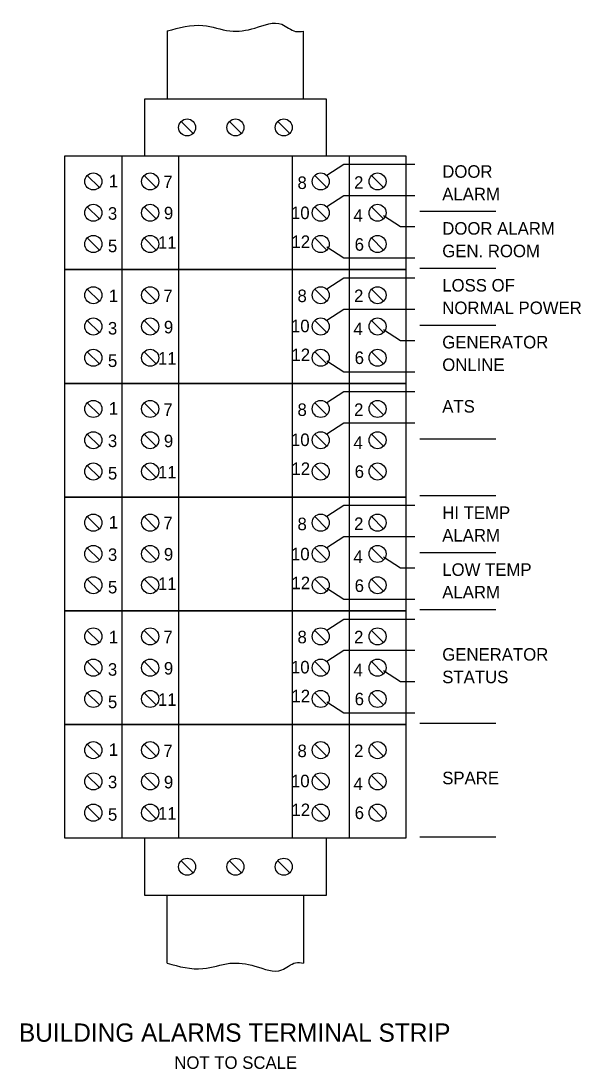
# Model space of a CAD drawing. Extents: x -0.178 to 0.269, y -0.328 to 0.508.
import ezdxf

# ---------------------------------------------------------------- set-up
doc = ezdxf.new("R2010")
doc.units = 0
doc.layers.add('GE_Pr_Notation', color=7, linetype='Continuous')
doc.layers.add('HS_Electrical_Devices', color=7, linetype='Continuous')

msp = doc.modelspace()

# ---------------------------------------------------------------- linework, layer by layer
at = {"layer": 'GE_Pr_Notation'}
for p, q in [((0.14026, 0.35631), (0.20079, 0.35631)), ((0.14026, 0.31091), (0.20079, 0.31091)), ((0.14026, 0.26552), (0.20079, 0.26552)), ((0.14026, 0.17473), (0.20079, 0.17473)), ((0.14026, 0.12938), (0.20079, 0.12938)), ((0.14026, 0.08394), (0.20079, 0.08394)), ((0.14026, 0.03854), (0.20079, 0.03854)), ((0.14026, -0.05225), (0.20079, -0.05225)), ((0.14026, -0.14307), (0.20079, -0.14307))]:
    msp.add_line(p, q, dxfattribs=at)
for points in [[(0.13613, 0.39372), (0.07935, 0.39372), (0.06581, 0.38494)], [(0.13613, 0.36876), (0.07935, 0.36876), (0.06581, 0.35998)], [(0.13613, 0.34379), (0.12475, 0.34379), (0.11121, 0.35257)], [(0.13613, 0.31882), (0.07935, 0.31882), (0.06581, 0.3276)], [(0.13613, 0.30293), (0.07935, 0.30293), (0.06581, 0.29416)], [(0.13613, 0.27797), (0.07935, 0.27797), (0.06581, 0.26919)], [(0.13613, 0.253), (0.12475, 0.253), (0.11121, 0.26178)], [(0.13613, 0.22803), (0.07935, 0.22803), (0.06581, 0.23681)], [(0.13613, 0.21215), (0.07935, 0.21215), (0.06581, 0.20337)], [(0.13613, 0.18718), (0.07935, 0.18718), (0.06581, 0.1784)], [(0.13613, 0.12136), (0.07935, 0.12136), (0.06581, 0.11258)], [(0.13613, 0.09639), (0.07935, 0.09639), (0.06581, 0.08761)], [(0.13613, 0.07142), (0.12475, 0.07142), (0.11121, 0.0802)], [(0.13613, 0.04645), (0.07935, 0.04645), (0.06581, 0.05523)], [(0.13613, 0.03057), (0.07935, 0.03057), (0.06581, 0.02179)], [(0.13613, 0.0056), (0.07935, 0.0056), (0.06581, -0.00318)], [(0.13613, -0.01937), (0.12475, -0.01937), (0.11121, -0.01059)], [(0.13613, -0.04434), (0.07935, -0.04434), (0.06581, -0.03556)]]:
    msp.add_lwpolyline(points, dxfattribs=at)
at = {"layer": 'HS_Electrical_Devices'}
for p, q in [((-0.06157, 0.50031), (-0.06157, 0.44595)), ((0.04738, 0.44595), (0.04738, 0.50021)), ((-0.0505, 0.42807), (-0.04087, 0.41844)), ((-0.01189, 0.42806), (-0.00226, 0.41843)), ((0.02668, 0.42807), (0.03631, 0.41844)), ((-0.09788, 0.40056), (-0.09788, 0.30977)), ((-0.05249, 0.40056), (-0.05249, 0.30977)), ((0.0383, 0.40056), (0.0383, 0.30977)), ((0.08369, 0.40056), (0.08369, 0.30977)), ((-0.1254, 0.38494), (-0.11577, 0.37532)), ((-0.08, 0.38494), (-0.07037, 0.37532)), ((0.05618, 0.38494), (0.06581, 0.37532)), ((0.10158, 0.38494), (0.11121, 0.37532)), ((-0.1254, 0.35998), (-0.11577, 0.35035)), ((-0.08, 0.35998), (-0.07037, 0.35035)), ((0.05618, 0.35998), (0.06581, 0.35035)), ((0.10158, 0.35998), (0.11121, 0.35035)), ((-0.1254, 0.33501), (-0.11577, 0.32538)), ((-0.08, 0.33501), (-0.07037, 0.32538)), ((0.05618, 0.33501), (0.06581, 0.32538)), ((0.10158, 0.33501), (0.11121, 0.32538)), ((-0.09788, 0.30977), (-0.09788, 0.21898)), ((-0.05249, 0.30977), (-0.05249, 0.21898)), ((0.0383, 0.30977), (0.0383, 0.21898)), ((0.08369, 0.30977), (0.08369, 0.21898)), ((-0.1254, 0.29416), (-0.11577, 0.28453)), ((-0.08, 0.29416), (-0.07037, 0.28453)), ((0.05618, 0.29416), (0.06581, 0.28453)), ((0.10158, 0.29416), (0.11121, 0.28453)), ((-0.1254, 0.26919), (-0.11577, 0.25956)), ((-0.08, 0.26919), (-0.07037, 0.25956)), ((0.05618, 0.26919), (0.06581, 0.25956)), ((0.10158, 0.26919), (0.11121, 0.25956)), ((-0.1254, 0.24422), (-0.11577, 0.23459)), ((-0.08, 0.24422), (-0.07037, 0.23459)), ((0.05618, 0.24422), (0.06581, 0.23459)), ((0.10158, 0.24422), (0.11121, 0.23459)), ((-0.09788, 0.21898), (-0.09788, 0.12819)), ((-0.05249, 0.21898), (-0.05249, 0.12819)), ((0.0383, 0.21898), (0.0383, 0.12819)), ((0.08369, 0.21898), (0.08369, 0.12819)), ((-0.1254, 0.20337), (-0.11577, 0.19374)), ((-0.08, 0.20337), (-0.07037, 0.19374)), ((0.05618, 0.20337), (0.06581, 0.19374)), ((0.10158, 0.20337), (0.11121, 0.19374)), ((-0.1254, 0.1784), (-0.11577, 0.16877)), ((-0.08, 0.1784), (-0.07037, 0.16877)), ((0.05618, 0.1784), (0.06581, 0.16877)), ((0.10158, 0.1784), (0.11121, 0.16877)), ((-0.1254, 0.15343), (-0.11577, 0.1438)), ((-0.08, 0.15343), (-0.07037, 0.1438)), ((0.05618, 0.15343), (0.06581, 0.1438)), ((0.10158, 0.15343), (0.11121, 0.1438)), ((-0.09788, 0.12819), (-0.09788, 0.0374)), ((-0.05249, 0.12819), (-0.05249, 0.0374)), ((0.0383, 0.12819), (0.0383, 0.0374)), ((0.08369, 0.12819), (0.08369, 0.0374)), ((-0.1254, 0.11258), (-0.11577, 0.10295)), ((-0.08, 0.11258), (-0.07037, 0.10295)), ((0.05618, 0.11258), (0.06581, 0.10295)), ((0.10158, 0.11258), (0.11121, 0.10295)), ((-0.1254, 0.08761), (-0.11577, 0.07798)), ((-0.08, 0.08761), (-0.07037, 0.07798)), ((0.05618, 0.08761), (0.06581, 0.07798)), ((0.10158, 0.08761), (0.11121, 0.07798)), ((-0.1254, 0.06264), (-0.11577, 0.05301)), ((-0.08, 0.06264), (-0.07037, 0.05301)), ((0.05618, 0.06264), (0.06581, 0.05301)), ((0.10158, 0.06264), (0.11121, 0.05301)), ((-0.09788, 0.0374), (-0.09788, -0.05339)), ((-0.05249, 0.0374), (-0.05249, -0.05339)), ((0.0383, 0.0374), (0.0383, -0.05339)), ((0.08369, 0.0374), (0.08369, -0.05339)), ((-0.1254, 0.02179), (-0.11577, 0.01216)), ((-0.08, 0.02179), (-0.07037, 0.01216)), ((0.05618, 0.02179), (0.06581, 0.01216)), ((0.10158, 0.02179), (0.11121, 0.01216)), ((-0.1254, -0.00318), (-0.11577, -0.01281)), ((-0.08, -0.00318), (-0.07037, -0.01281)), ((0.05618, -0.00318), (0.06581, -0.01281)), ((0.10158, -0.00318), (0.11121, -0.01281)), ((-0.1254, -0.02815), (-0.11577, -0.03778)), ((-0.08, -0.02815), (-0.07037, -0.03778)), ((0.05618, -0.02815), (0.06581, -0.03778)), ((0.10158, -0.02815), (0.11121, -0.03778)), ((-0.09788, -0.05339), (-0.09788, -0.14418)), ((-0.05249, -0.05339), (-0.05249, -0.14418)), ((0.0383, -0.05339), (0.0383, -0.14418)), ((0.08369, -0.05339), (0.08369, -0.14418)), ((-0.1254, -0.069), (-0.11577, -0.07863)), ((-0.08, -0.069), (-0.07037, -0.07863)), ((0.05618, -0.069), (0.06581, -0.07863)), ((0.10158, -0.069), (0.11121, -0.07863)), ((-0.1254, -0.09397), (-0.11577, -0.1036)), ((-0.08, -0.09397), (-0.07037, -0.1036)), ((0.05618, -0.09397), (0.06581, -0.1036)), ((0.10158, -0.09397), (0.11121, -0.1036)), ((-0.1254, -0.11894), (-0.11577, -0.12857)), ((-0.08, -0.11894), (-0.07037, -0.12857)), ((0.05618, -0.11894), (0.06581, -0.12857)), ((0.10158, -0.11894), (0.11121, -0.12857)), ((-0.0505, -0.16206), (-0.04087, -0.17169)), ((-0.0505, -0.16206), (-0.04087, -0.17169)), ((-0.01189, -0.16207), (-0.00226, -0.1717)), ((-0.01189, -0.16207), (-0.00226, -0.1717)), ((0.02668, -0.16206), (0.03631, -0.17169)), ((0.02668, -0.16206), (0.03631, -0.17169)), ((-0.06157, -0.24393), (-0.06157, -0.18957)), ((0.04738, -0.18957), (0.04738, -0.24383))]:
    msp.add_line(p, q, dxfattribs=at)
for points in [[(-0.07973, 0.44595), (-0.07973, 0.40056), (0.06554, 0.40056), (0.06554, 0.44595)], [(0.12909, 0.40056), (0.12909, 0.30977), (-0.14328, 0.30977), (-0.14328, 0.40056)], [(0.12909, 0.30977), (0.12909, 0.21898), (-0.14328, 0.21898), (-0.14328, 0.30977)], [(0.12909, 0.21898), (0.12909, 0.12819), (-0.14328, 0.12819), (-0.14328, 0.21898)], [(0.12909, 0.12819), (0.12909, 0.0374), (-0.14328, 0.0374), (-0.14328, 0.12819)], [(0.12909, 0.0374), (0.12909, -0.05339), (-0.14328, -0.05339), (-0.14328, 0.0374)], [(0.12909, -0.05339), (0.12909, -0.14418), (-0.14328, -0.14418), (-0.14328, -0.05339)], [(-0.07973, -0.14418), (-0.07973, -0.18957), (0.06554, -0.18957), (0.06554, -0.14418)]]:
    msp.add_lwpolyline(points, close=True, dxfattribs=at)
for centre in [(-0.04568, 0.42325), (-0.00708, 0.42325), (0.03149, 0.42325), (-0.12058, 0.38013), (-0.07519, 0.38013), (0.061, 0.38013), (0.10639, 0.38013), (-0.12058, 0.35516), (-0.07519, 0.35516), (0.061, 0.35516), (0.10639, 0.35516), (-0.12058, 0.3302), (-0.07519, 0.3302), (0.061, 0.3302), (0.10639, 0.3302), (-0.12058, 0.28934), (-0.07519, 0.28934), (0.061, 0.28934), (0.10639, 0.28934), (-0.12058, 0.26437), (-0.07519, 0.26437), (0.061, 0.26437), (0.10639, 0.26437), (-0.12058, 0.23941), (-0.07519, 0.23941), (0.061, 0.23941), (0.10639, 0.23941), (-0.12058, 0.19855), (-0.07519, 0.19855), (0.061, 0.19855), (0.10639, 0.19855), (-0.12058, 0.17358), (-0.07519, 0.17358), (0.061, 0.17358), (0.10639, 0.17358), (-0.12058, 0.14862), (-0.07519, 0.14862), (0.061, 0.14862), (0.10639, 0.14862), (-0.12058, 0.10776), (-0.07519, 0.10776), (0.061, 0.10776), (0.10639, 0.10776), (-0.12058, 0.08279), (-0.07519, 0.08279), (0.061, 0.08279), (0.10639, 0.08279), (-0.12058, 0.05783), (-0.07519, 0.05783), (0.061, 0.05783), (0.10639, 0.05783), (-0.12058, 0.01697), (-0.07519, 0.01697), (0.061, 0.01697), (0.10639, 0.01697), (-0.12058, -0.008), (-0.07519, -0.008), (0.061, -0.008), (0.10639, -0.008), (-0.12058, -0.03296), (-0.07519, -0.03296), (0.061, -0.03296), (0.10639, -0.03296), (-0.12058, -0.07382), (-0.07519, -0.07382), (0.061, -0.07382), (0.10639, -0.07382), (-0.12058, -0.09878), (-0.07519, -0.09878), (0.061, -0.09878), (0.10639, -0.09878), (-0.12058, -0.12375), (-0.07519, -0.12375), (0.061, -0.12375), (0.10639, -0.12375), (-0.04568, -0.16688), (-0.00708, -0.16688), (0.03149, -0.16688)]:
    msp.add_circle(centre, 0.00681, dxfattribs=at)
for points in [[(-0.06157, 0.50031), (-0.03301, 0.50463), (-0.01147, 0.50036), (0.00845, 0.50259), (0.02999, 0.50564), (0.04096, 0.49995), (0.04738, 0.50021)], [(-0.06157, -0.24393), (-0.03301, -0.24825), (-0.01147, -0.24398), (0.00845, -0.24622), (0.02999, -0.24927), (0.04096, -0.24357), (0.04738, -0.24383)]]:
    msp.add_spline(points, degree=3, dxfattribs=at)

# ---------------------------------------------------------------- texts
at = {"layer": 'GE_Pr_Notation'}
for s, height, p in [('DOOR', 0.01, (0.15806, 0.38308)), ('1', 0.01, (-0.10817, 0.37546)), ('7', 0.01, (-0.06465, 0.37487)), ('8', 0.01, (0.04246, 0.37412)), ('2', 0.01, (0.08765, 0.37428)), ('ALARM', 0.01, (0.15806, 0.36508)), ('9', 0.01, (-0.06422, 0.34991)), ('10', 0.01, (0.03726, 0.35007)), ('3', 0.01, (-0.10891, 0.34959)), ('4', 0.01, (0.08714, 0.34792)), ('DOOR ALARM', 0.01, (0.15806, 0.33767)), ('11', 0.01, (-0.06896, 0.3264)), ('12', 0.01, (0.03764, 0.32704)), ('6', 0.01, (0.08811, 0.32484)), ('5', 0.01, (-0.10891, 0.32365)), ('GEN. ROOM', 0.01, (0.15806, 0.31967)), ('LOSS OF', 0.01, (0.15806, 0.29226)), ('1', 0.01, (-0.10817, 0.28384)), ('7', 0.01, (-0.06465, 0.28384)), ('8', 0.01, (0.04246, 0.28384)), ('2', 0.01, (0.08765, 0.28384)), ('NORMAL POWER', 0.01, (0.15806, 0.27426)), ('3', 0.01, (-0.10891, 0.25796)), ('9', 0.01, (-0.06422, 0.25888)), ('10', 0.01, (0.03726, 0.25979)), ('4', 0.01, (0.08714, 0.25748)), ('GENERATOR', 0.01, (0.15806, 0.24685)), ('11', 0.01, (-0.06896, 0.23391)), ('12', 0.01, (0.03764, 0.23676)), ('6', 0.01, (0.08811, 0.2344)), ('5', 0.01, (-0.10891, 0.23203)), ('ONLINE', 0.01, (0.15806, 0.22885)), ('1', 0.01, (-0.10817, 0.19399)), ('7', 0.01, (-0.06465, 0.19297)), ('8', 0.01, (0.04246, 0.19297)), ('2', 0.01, (0.08765, 0.19297)), ('ATS', 0.01, (0.15806, 0.19561)), ('3', 0.01, (-0.10891, 0.16811)), ('9', 0.01, (-0.06422, 0.16801)), ('10', 0.01, (0.03726, 0.16892)), ('4', 0.01, (0.08714, 0.16661)), ('5', 0.01, (-0.10891, 0.14218)), ('11', 0.01, (-0.06896, 0.14304)), ('12', 0.01, (0.03764, 0.14589)), ('6', 0.01, (0.08811, 0.14353)), ('HI TEMP', 0.01, (0.15806, 0.11071)), ('1', 0.01, (-0.10817, 0.1031)), ('7', 0.01, (-0.06465, 0.1025)), ('8', 0.01, (0.04246, 0.10175)), ('2', 0.01, (0.08765, 0.10191)), ('ALARM', 0.01, (0.15806, 0.09271)), ('3', 0.01, (-0.10891, 0.07722)), ('9', 0.01, (-0.06422, 0.07754)), ('10', 0.01, (0.03726, 0.0777)), ('4', 0.01, (0.08714, 0.07555)), ('LOW TEMP', 0.01, (0.15806, 0.0653)), ('5', 0.01, (-0.10891, 0.05129)), ('11', 0.01, (-0.06896, 0.05403)), ('12', 0.01, (0.03764, 0.05467)), ('6', 0.01, (0.08811, 0.05247)), ('ALARM', 0.01, (0.15806, 0.0473)), ('1', 0.01, (-0.10817, 0.01147)), ('7', 0.01, (-0.06465, 0.01147)), ('8', 0.01, (0.04246, 0.01147)), ('2', 0.01, (0.08765, 0.01147)), ('GENERATOR', 0.01, (0.15806, -0.00239)), ('3', 0.01, (-0.10891, -0.01441)), ('9', 0.01, (-0.06422, -0.01349)), ('10', 0.01, (0.03726, -0.01258)), ('4', 0.01, (0.08714, -0.01489)), ('STATUS', 0.01, (0.15806, -0.02039)), ('5', 0.01, (-0.10891, -0.04034)), ('11', 0.01, (-0.06896, -0.03846)), ('12', 0.01, (0.03764, -0.0356)), ('6', 0.01, (0.08811, -0.03797)), ('1', 0.01, (-0.10817, -0.07838)), ('7', 0.01, (-0.06465, -0.0794)), ('8', 0.01, (0.04246, -0.0794)), ('2', 0.01, (0.08765, -0.0794)), ('SPARE', 0.01, (0.15806, -0.10103)), ('3', 0.01, (-0.10891, -0.10425)), ('9', 0.01, (-0.06422, -0.10436)), ('10', 0.01, (0.03726, -0.10345)), ('4', 0.01, (0.08714, -0.10576)), ('12', 0.01, (0.03764, -0.12647)), ('5', 0.01, (-0.10891, -0.13019)), ('11', 0.01, (-0.06896, -0.12933)), ('6', 0.01, (0.08811, -0.12884)), ('BUILDING ALARMS TERMINAL STRIP', 0.0145833, (-0.17997, -0.30658)), ('NOT TO SCALE', 0.01, (-0.05591, -0.32825))]:
    msp.add_text(s, height=height, rotation=360, dxfattribs=at).set_placement(p)

doc.saveas('drawing.dxf')
